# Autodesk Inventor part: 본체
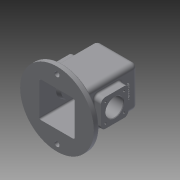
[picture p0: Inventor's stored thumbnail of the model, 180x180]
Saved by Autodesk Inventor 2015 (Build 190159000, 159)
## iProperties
Created: 2021-08
Part Number: 본체
Material: 일반
Document SubType Name: Modeling
Designer: 103-20
Density: 1 g/cm^3
Appearance: 기본값
Mass: 246.458 g
Surface Area: 996.247 cm^2
Volume: 246.458 cm^3
Author: 103-20
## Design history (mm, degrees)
sketch "스케치1"
  geometry: C1 r 67 at (0, 0); 1 further point
  constraints: 1 centre point, 1 coincident
  dimensions: "d0" = 134 diameter of C1
extrude "돌출1" new body sketch "스케치1" distance "d1" = 10; taper "d2" = 0 deg
sketch "스케치2"
  geometry: C1 r 67 at (0, 0) reference; C2 r 4.5 at (0, 55); C3 r 4.5 at (0, -55); A1 r 55 centre (0, 0) between (0, 55) and (0, -55)
  constraints: 3 centre point, 2 point on circle, 1 coincident
  dimensions: "d3" = 110 diameter of A1; "d4" = 9 diameter of C2; "d5" = 9 diameter of C3
extrude "돌출2" cut sketch "스케치2" distance "d6" = 10; taper "d7" = 0 deg
sketch "스케치3"
  geometry: L1 (37, -37)-(-37, -37); L2 (-37, -37)-(-37, 37); L3 (-37, 37)-(37, 37); L4 (37, 37)-(37, -37); L5 (37, -37)-(-37, 37); L6 (-37, -37)-(37, 37); C1 r 67 at (0, 0) reference
  constraints: 12 end point, 2 midpoint, 2 parallel, 1 horizontal, 1 perpendicular
  dimensions: "d8" = 74 distance of L2.end L3.end; "d9" = 74 distance of L3.end L1.start
extrude "돌출3" join sketch "스케치3" distance "d10" = 100; taper "d11" = 0 deg
sketch "스케치4"
  geometry: C1 r 20 at (0, 0); 1 further point
  constraints: 1 centre point, 1 coincident
  dimensions: "d12" = 40 diameter of C1
extrude "돌출4" join sketch "스케치4" distance "d13" = 10; taper "d14" = 0 deg
sketch "스케치5"
  geometry: L1 (0, 100)-(74, 100) reference; L2 (12, 70)-(62, 70); L3 (62, 70)-(62, 20); L4 (62, 20)-(12, 20); L5 (12, 20)-(12, 70); L6 (12, 70)-(62, 20); L7 (62, 70)-(12, 20); L8 (-30, -10)-(104, -10) reference; 4 further points
  constraints: 12 end point, 4 midpoint, 2 parallel, 1 horizontal, 1 perpendicular, 1 vertical alignment
  dimensions: "d15" = 50 distance of L2.start L2.end; "d16" = 50 distance of L2.end L3.end; "d17" = 55 distance from line of L8 point (37, 45); "d18" = 37 horizontal distance of L1.start point (37, 45) (derived)
extrude "돌출5" join sketch "스케치5" distance "d19" = 13; taper "d20" = 0 deg
sketch "스케치6"
  geometry: L1 (32, -32)-(-32, -32); L2 (-32, -32)-(-32, 32); L3 (-32, 32)-(32, 32); L4 (32, 32)-(32, -32); L5 (32, -32)-(-32, 32); L6 (-32, -32)-(32, 32); C1 r 67 at (0, 0) reference
  constraints: 12 end point, 2 midpoint, 2 parallel, 1 horizontal, 1 perpendicular
  dimensions: "d21" = 64 distance of L2.end L3.end; "d22" = 64 distance of L3.end L1.start
extrude "돌출6" cut sketch "스케치6" distance "d23" = 105; taper "d24" = 0 deg
fillet "모깎기1" dims "d25" = 3
sketch "스케치9"
  geometry: L1 (58, 0)-(0, 0) reference; L2 (-38, 0)-(96, 0) reference; L3 (-8, 10)-(-8, 110) reference; C1 r 25 at (29, 55); 2 further points
  constraints: 1 centre point, 1 midpoint, 1 vertical alignment
  dimensions: "d31" = 55 distance from line of L2 C1.centre; "d32" = 37 distance from line of L3 C1.centre (derived); "d40" = 50 diameter of C1
extrude "돌출7" join sketch "스케치9" distance "d33" = 7; taper "d34" = -20 deg
sketch "스케치10"
  geometry: L1 (-30, -10)-(104, -10) reference; L2 (0, 0)-(0, 100) reference; C1 r 16 at (37, 45); 1 further point
  constraints: 1 centre point
  dimensions: "d35" = 32 diameter of C1; "d36" = 55 distance from line of L1 C1.centre; "d37" = 37 distance from line of L2 C1.centre
extrude "돌출8" cut sketch "스케치10" distance "d38" = 30; taper "d39" = 0 deg
fillet "모깎기3" dims "d42" = 8
fillet "모깎기4" dims "d43" = 3
sketch "스케치13"
  geometry: A1 r 8 centre (20, 62) between (20, 70) and (12, 62) reference; A2 r 8 centre (20, 28) between (12, 28) and (20, 20) reference; A3 r 8 centre (54, 28) between (54, 20) and (62, 28) reference; A4 r 8 centre (54, 62) between (62, 62) and (54, 70) reference; 1 further point
hole "구멍2" sketch "스케치13" at (54, 62), (54, 28), (20, 62), (20, 28) diameter "d51" = 3.242; stored, may be unused: countersink angle "d55" = 90 deg, drill point angle "d57" = 118 deg; dims "d52" = 8, "d53" = 4, "d54" = 2, "d56" = 10
sketch "스케치14"
  geometry: C1 r 20 at (0, 0) reference; C2 r 14 at (0, 0)
  constraints: 1 centre point, 1 coincident
  dimensions: "d58" = 28 diameter of C2
extrude "돌출9" cut sketch "스케치14" distance "d59" = 4; taper "d60" = 0 deg
sketch "스케치15"
  geometry: C1 r 14 at (0, 0) reference; C2 r 10.5 at (0, 0)
  constraints: 1 centre point, 1 coincident
  dimensions: "d61" = 21 diameter of C2
extrude "돌출10" cut sketch "스케치15" distance "d62" = 20; taper "d63" = 0 deg
fillet "모깎기5" dims "d64" = 3
fillet "모깎기6" dims "d65" = 8
fillet "모깎기7" dims "d66" = 3
sketch "스케치16"
  geometry: L1 (49, 18)-(9, 18) reference; L2 (-8, 0)-(-8, -89) reference; 2 further points
  constraints: 1 other
  dimensions: "d67" = 28 distance from line of L1 point (29, -10); "d68" = 37 distance from line of L2 point (29, -10)
feature "엠보싱1" sketch "스케치16" dims "d69" = 1, "d70" = 0
fillet "모깎기8" dims "d71" = 3
chamfer "모따기1" distance "d72" = 1; stored, may be unused: second distance "d73" = 2, angle "d74" = 45 deg
node "솔리드1"
mirror "대칭1"
mirror "대칭2"
